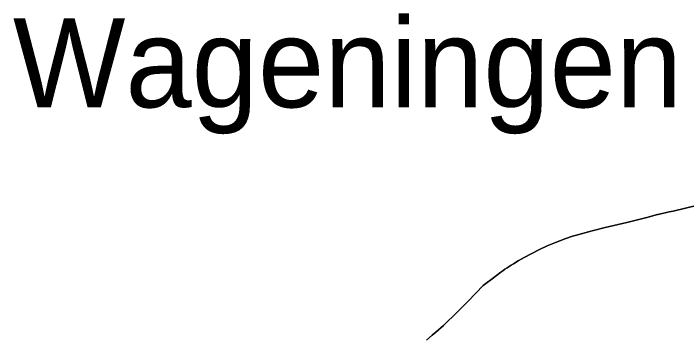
# Model space of a CAD drawing. Extents: x 113371 to 291721, y 393993 to 520143.
# Drawn here: x 172120 to 175896, y 440664 to 442483 of the extents above; entities that cross this region are included whole.
import ezdxf

# ---------------------------------------------------------------- set-up
doc = ezdxf.new("R2010")
doc.units = 0
for name, color, linetype in [('Default', 7, 'Continuous'), ('Gemeentegrenzen', 7, 'Continuous'), ('Woonplaatsnamen', 7, 'Continuous')]:
    doc.layers.add(name, color=color, linetype=linetype)

msp = doc.modelspace()

# ---------------------------------------------------------------- linework, layer by layer
at = {"layer": 'Default'}
msp.add_lwpolyline([(175959.945, 441407.043), (175889.413, 441390.339), (175821.119, 441374.212), (175798.586, 441369.49), (175736.228, 441354.922), (175732.979, 441354.057), (175672.525, 441338.323), (175560.347, 441310.748), (175438.66, 441280.938), (175366.599, 441262.457), (175271.806, 441237.121), (175257.097, 441232.949), (175218.022, 441219.54), (175152.206, 441193.77), (175113.578, 441178.129), (175067.375, 441157.128), (174985.816, 441113.941), (174950.905, 441095.177), (174924.909, 441078.351), (174912.908, 441070.7), (174900.944, 441062.992), (174889.016, 441055.227), (174877.126, 441047.406), (174865.272, 441039.529), (174853.456, 441031.596), (174805.032, 440994.671), (174769.976, 440968.02), (174762.697, 440961.916), (174756.014, 440955.515), (174671.653, 440868.873), (174611.798, 440809.027), (174533.525, 440732.656), (174488.816, 440694.096), (174469.169, 440677.398), (174437.627, 440649.277)], dxfattribs=at)
at = {"layer": 'Gemeentegrenzen'}
for p, q in [((175798.586, 441369.49), (175821.119, 441374.212)), ((175366.599, 441262.457), (175438.66, 441280.938)), ((175438.66, 441280.938), (175560.347, 441310.748)), ((175271.806, 441237.121), (175366.599, 441262.457)), ((175152.206, 441193.77), (175218.022, 441219.54)), ((175218.022, 441219.54), (175257.097, 441232.949)), ((175257.097, 441232.949), (175271.806, 441237.121)), ((175113.578, 441178.129), (175152.206, 441193.77)), ((174900.944, 441062.992), (174912.908, 441070.7)), ((174912.908, 441070.7), (174924.909, 441078.351)), ((174853.456, 441031.596), (174865.272, 441039.529)), ((174865.272, 441039.529), (174877.126, 441047.406)), ((174671.653, 440868.873), (174756.014, 440955.515)), ((174437.627, 440649.277), (174469.169, 440677.398))]:
    msp.add_line(p, q, dxfattribs=at)
for points in [[(174437.627, 440649.277), (174469.169, 440677.398), (174488.816, 440694.096), (174533.525, 440732.656), (174611.798, 440809.027), (174671.653, 440868.873), (174756.014, 440955.515), (174762.697, 440961.916), (174769.976, 440968.02), (174805.032, 440994.671), (174853.456, 441031.596), (174865.272, 441039.529), (174877.126, 441047.406), (174889.016, 441055.227), (174900.944, 441062.992), (174912.908, 441070.7), (174924.909, 441078.351), (174950.905, 441095.177), (174985.816, 441113.941), (175067.375, 441157.128), (175113.578, 441178.129), (175152.206, 441193.77), (175218.022, 441219.54), (175257.097, 441232.949), (175271.806, 441237.121), (175366.599, 441262.457), (175438.66, 441280.938), (175560.347, 441310.748), (175672.525, 441338.323), (175732.979, 441354.057), (175736.228, 441354.922), (175798.586, 441369.49), (175821.119, 441374.212), (175889.413, 441390.339), (175959.945, 441407.043)], [(175959.945, 441407.043), (175889.413, 441390.339), (175821.119, 441374.212), (175798.586, 441369.49), (175736.228, 441354.922), (175732.979, 441354.057), (175672.525, 441338.323), (175560.347, 441310.748), (175438.66, 441280.938), (175366.599, 441262.457), (175271.806, 441237.121), (175257.097, 441232.949), (175218.022, 441219.54), (175152.206, 441193.77), (175113.578, 441178.129), (175067.375, 441157.128), (174985.816, 441113.941), (174950.905, 441095.177), (174924.909, 441078.351), (174912.908, 441070.7), (174900.944, 441062.992), (174889.016, 441055.227), (174877.126, 441047.406), (174865.272, 441039.529), (174853.456, 441031.596), (174805.032, 440994.671), (174769.976, 440968.02), (174762.697, 440961.916), (174756.014, 440955.515), (174671.653, 440868.873), (174611.798, 440809.027), (174533.525, 440732.656), (174488.816, 440694.096), (174469.169, 440677.398), (174437.627, 440649.277)], [(175821.119, 441374.212), (175889.413, 441390.339), (175959.945, 441407.043)], [(175560.347, 441310.748), (175672.525, 441338.323), (175732.979, 441354.057)], [(175732.979, 441354.057), (175736.228, 441354.922), (175798.586, 441369.49)], [(174985.816, 441113.941), (175067.375, 441157.128), (175113.578, 441178.129)], [(174924.909, 441078.351), (174950.905, 441095.177), (174985.816, 441113.941)], [(174877.126, 441047.406), (174889.016, 441055.227), (174900.944, 441062.992)], [(174769.976, 440968.02), (174805.032, 440994.671), (174853.456, 441031.596)], [(174756.014, 440955.515), (174762.697, 440961.916), (174769.976, 440968.02)], [(174469.169, 440677.398), (174488.816, 440694.096), (174533.525, 440732.656), (174611.798, 440809.027), (174671.653, 440868.873)]]:
    msp.add_lwpolyline(points, dxfattribs=at)

# ---------------------------------------------------------------- texts
at = {"layer": 'Woonplaatsnamen'}
msp.add_text('Wageningen', height=500, dxfattribs=at).set_placement((172117.282, 441956.169))

doc.saveas('drawing.dxf')
